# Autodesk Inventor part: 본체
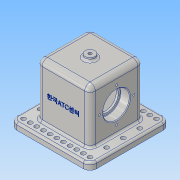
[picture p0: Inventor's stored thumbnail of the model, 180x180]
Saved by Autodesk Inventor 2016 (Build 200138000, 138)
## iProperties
Created: 2018-11
Part Number: 본체
Material: 알루미늄 6061
Document SubType Name: Modeling
Designer: 605-15
Density: 2.7 g/cm^3
Appearance: 알루미늄 - 평지
Mass: 1016.99 g
Surface Area: 777.082 cm^2
Volume: 376.663 cm^3
Author: 605-15
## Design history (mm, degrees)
sketch "스케치1"
  geometry: L1 (-60, 60)-(60, 60); L2 (60, 60)-(60, -60); L3 (60, -60)-(-60, -60); L4 (-60, -60)-(-60, 60); L5 (-60, 60)-(60, -60); L6 (60, 60)-(-60, -60); 1 further point
  constraints: 12 end point, 2 midpoint, 2 parallel, 1 horizontal, 1 perpendicular
  dimensions: "d0" = 120 distance of L2.end L3.end; "d1" = 119.99999 distance of L1.end L2.end
extrude "돌출1" new body sketch "스케치1" distance "d2" = 10; taper "d3" = 0 deg
sketch "스케치2"
  geometry: L1 (40, -40)-(-40, -40); L2 (-40, -40)-(-40, 40); L3 (-40, 40)-(40, 40); L4 (40, 40)-(40, -40); L5 (40, -40)-(-40, 40); L6 (-40, -40)-(40, 40); 1 further point
  constraints: 12 end point, 2 midpoint, 2 parallel, 1 horizontal, 1 perpendicular
  dimensions: "d4" = 80 distance of L1.end L2.end; "d5" = 80 distance of L1.start L1.end
extrude "돌출2" join sketch "스케치2" distance "d6" = 80; taper "d7" = 0 deg
fillet "모깎기1" dims "d8" = 10
fillet "모깎기2" dims "d9" = 3
fillet "모깎기3" dims "d10" = 8
fillet "모깎기4" dims "d11" = 3
sketch "스케치6"
  geometry: L1 (-40, 13)-(-40, 87) reference; L2 (40, 87)-(40, 13) reference; L3 (-40, 48)-(40, 48); L4 (-50, 0)-(50, 0) reference; L5 (-40, 48)-(-40, 68); L6 (-26, 68)-(-26, 64.5); L7 (-40, 68)-(-26, 68); L8 (26, 64.5)-(26, 68); L9 (26, 68)-(40, 68); L10 (-26, 64.5)-(26, 64.5); L11 (40, 68)-(40, 48); 1 further point
  constraints: 16 end point, 4 point on line, 3 perpendicular, 2 horizontal, 1 vertical
  dimensions: "d12" = 48 distance between parallel lines of L4 L3; "d13" = 14 distance of L5.end L6.start; "d16" = 14 distance of L8.end L9.end; "d17" = 20 distance between parallel lines of L3 L7; "d19" = 20 distance between parallel lines of L3 L9; "d20" = 16.5 distance between parallel lines of L3 L10
revolve "회전1" sketch "스케치6" stored, may be unused: angle "d21" = 90 deg
sketch "스케치7"
  geometry: 1 further point
chamfer "모따기1" distance "d22" = 1; stored, may be unused: second distance "d23" = 2, angle "d24" = 45 deg
fillet "모깎기5" dims "d25" = 0.6
sketch "스케치8"
  geometry: L1 (23, 30)-(-23, 30); L2 (-23, 30)-(-23, -30); L3 (-23, -30)-(23, -30); L4 (23, -30)-(23, 30); L5 (23, 30)-(-23, -30); L6 (-23, 30)-(23, -30); 1 further point
  constraints: 12 end point, 2 midpoint, 2 parallel, 1 horizontal, 1 perpendicular
  dimensions: "d26" = 46 distance of L2.end L3.end; "d27" = 60 distance of L1.end L2.end
extrude "돌출3" cut sketch "스케치8" distance "d28" = 80; taper "d29" = 0 deg
fillet "모깎기6" dims "d30" = 3
fillet "모깎기7" dims "d31" = 3
sketch "스케치9"
  geometry: C1 r 7.5 at (0, 0); 1 further point
  constraints: 1 centre point, 1 coincident
  dimensions: "d32" = 15 diameter of C1
extrude "돌출4" join sketch "스케치9" distance "d33" = 5; taper "d34" = 0 deg
fillet "모깎기8" dims "d35" = 3
sketch "스케치11"
  geometry: C1 r 7.5 at (0, 0) reference; 1 further point
  constraints: 1 coincident
hole "구멍1" sketch "스케치11" at (0, 0) diameter "d36" = 4.917; stored, may be unused: countersink angle "d40" = 90 deg, drill point angle "d42" = 118 deg; dims "d37" = 20, "d38" = 4, "d39" = 2, "d41" = 17.1
sketch "스케치13" dims "d43" = 52
  geometry: C1 r 21 at (32, 35) reference; 3 further points
  constraints: 2 vertical alignment, 1 coincident, 2 other
hole "구멍2" sketch "스케치13" at (32, 61) diameter "d44" = 3.242; stored, may be unused: countersink angle "d48" = 90 deg, drill point angle "d50" = 118 deg; dims "d45" = 8, "d46" = 4, "d47" = 2, "d49" = 10
sketch "스케치14"
  geometry: A1 r 7 centre (-50, 50) between (-50, 57) and (-57, 50) reference; 1 further point
hole "구멍3" sketch "스케치14" at (-50, 50) diameter "d54" = 6.6; stored, may be unused: countersink angle "d58" = 90 deg, drill point angle "d60" = 118 deg; dims "d55" = 8, "d56" = 4, "d57" = 2, "d59" = 10
sketch "스케치16"
  geometry: L1 (92, -87)-(82, -87) reference; L2 (82, -87)-(-18, -87) reference; 3 further points
  constraints: 1 midpoint, 1 vertical alignment, 1 other
  dimensions: "d67" = 48 distance from line of L1 point (32, -39)
feature "엠보싱1" sketch "스케치16" dims "d68" = 0.5, "d69" = 0
sketch "스케치18"
  geometry: L1 (37, 32)-(37, -32) reference; L2 (-32, 37)-(32, 37) reference; L3 (-37, -32)-(-37, 32) reference; L4 (32, -37)-(-32, -37) reference; L5 (40, -40)-(-40, -40); L6 (-40, -40)-(-40, 40); L7 (-40, 40)-(40, 40); L8 (40, 40)-(40, -40); L9 (40, -40)-(-40, 40); L10 (-40, -40)-(40, 40); C1 r 10.5 at (0, 0) reference; A1 r 5 centre (32, 32) between (37, 32) and (32, 37) reference; A2 r 5 centre (-32, 32) between (-32, 37) and (-37, 32) reference; A3 r 5 centre (-32, -32) between (-37, -32) and (-32, -37) reference; A4 r 5 centre (32, -32) between (32, -37) and (37, -32) reference
  constraints: 12 end point, 2 midpoint, 2 parallel, 1 horizontal, 1 perpendicular
  dimensions: "d70" = 80 distance of L6.end L7.end; "d71" = 80 distance of L5.end L6.end
extrude "돌출5" join sketch "스케치18" distance "d72" = 5; taper "d73" = 0 deg
fillet "모깎기9" dims "d74" = 8
fillet "모깎기10" dims "d75" = 8
node "솔리드1"
pattern_circular "원형 패턴1" dims angle "d52" = 360 deg
mirror "대칭1"
pattern_linear "직사각형 패턴1" dims "d63" = 10
pattern_linear "직사각형 패턴2" dims "d66" = 25
mirror "대칭2"
mirror "대칭3"
